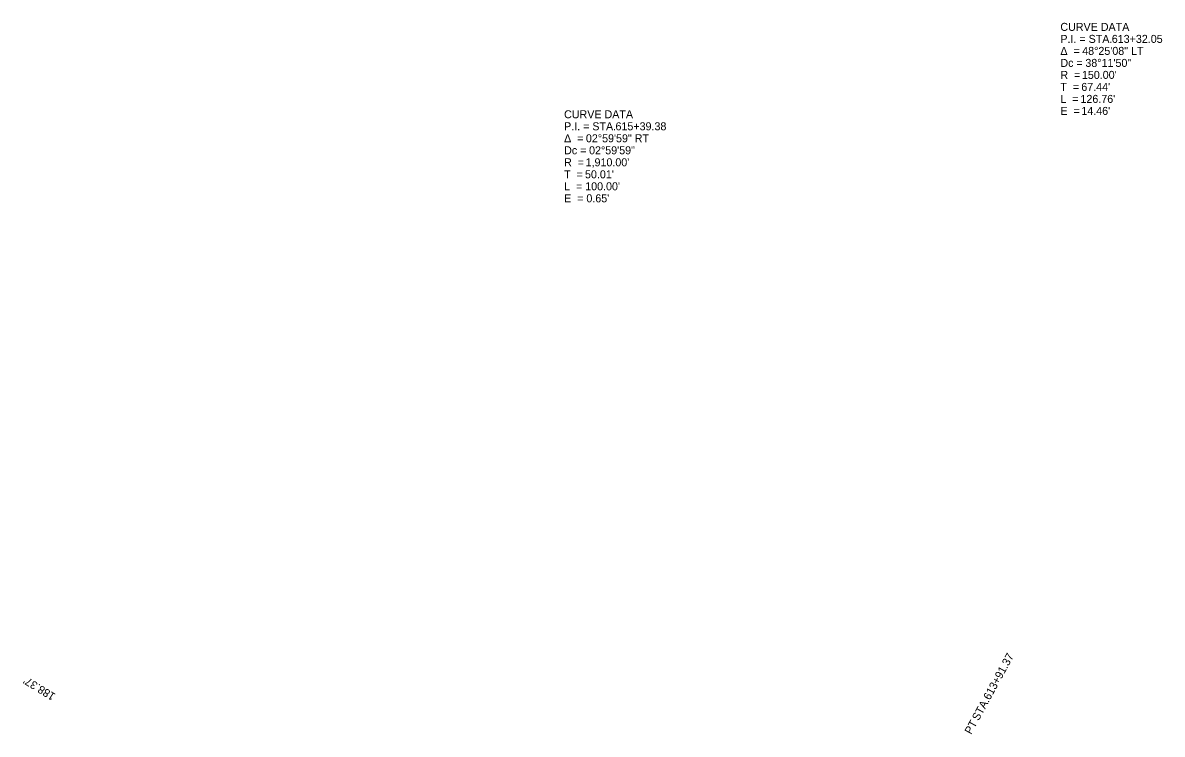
# Model space of a CAD drawing. Extents: x 1507135 to 1508660, y 327655 to 329219.
# Drawn here: x 1507283.8 to 1507682.5, y 328623.1 to 328872 of the extents above; entities that cross this region are included whole.
import ezdxf

# ---------------------------------------------------------------- set-up
doc = ezdxf.new("R2010")
doc.units = 0
for name, color, linetype in [('GE_X_Alignment_100_Cardinal_Points', 7, 'Continuous'), ('GE_X_Alignment_100_Curve_Data', 7, 'Continuous'), ('GE_X_Alignment_500_Curve_Data', 7, 'Continuous'), ('GE_X_Alignment_500_Distances', 7, 'Continuous')]:
    doc.layers.add(name, color=color, linetype=linetype)

msp = doc.modelspace()

# ---------------------------------------------------------------- texts
at = {"layer": 'GE_X_Alignment_100_Cardinal_Points'}
for s, p in [('613+91.37', (1507622.17, 328634.8)), (' STA. ', (1507617.71, 328626.62)), ('PT', (1507615.63, 328622.8))]:
    msp.add_text(s, height=2.8, rotation=61.3965, dxfattribs=at).set_placement(p)
at = {"layer": 'GE_X_Alignment_100_Curve_Data'}
for s, p in [('CURVE DATA', (1507473.2, 328838.6)), ('P.I. = STA. ', (1507473.2, 328834.4)), ('615+39.38', (1507491.19, 328834.4)), ('Δ  = ', (1507473.2, 328830.2)), ('02°59\'59" RT', (1507480.84, 328830.2)), ('Dc = ', (1507473.2, 328826)), ('02°59\'59"', (1507481.94, 328826)), ('R  = ', (1507473.2, 328821.8)), ("1,910.00'", (1507480.73, 328821.8)), ('T  = ', (1507473.2, 328817.6)), ("50.01'", (1507480.52, 328817.6)), ("L  = 100.00'", (1507473.2, 328813.4)), ("E  = 0.65'", (1507473.2, 328809.2))]:
    msp.add_text(s, height=2.8, dxfattribs=at).set_placement(p)
at = {"layer": 'GE_X_Alignment_500_Curve_Data'}
for s, p in [('CURVE DATA', (1507646.87, 328869.18)), ('P.I. = STA. ', (1507646.87, 328864.98)), ('613+32.05', (1507664.86, 328864.98)), ('Δ  = ', (1507646.87, 328860.78)), ('48°25\'08" LT', (1507654.51, 328860.78)), ('Dc = ', (1507646.87, 328856.58)), ('38°11\'50"', (1507655.61, 328856.58)), ('R  = ', (1507646.87, 328852.38)), ("150.00'", (1507654.4, 328852.38)), ('T  = ', (1507646.87, 328848.18)), ("67.44'", (1507654.19, 328848.18)), ('L  = ', (1507646.87, 328843.98)), ("126.76'", (1507653.9, 328843.98)), ('E  = ', (1507646.87, 328839.78)), ("14.46'", (1507654.21, 328839.78))]:
    msp.add_text(s, height=2.8, dxfattribs=at).set_placement(p)
at = {"layer": 'GE_X_Alignment_500_Distances'}
msp.add_text("188.37'", height=2.8, rotation=148.3965, dxfattribs=at).set_placement((1507295.45, 328637.05))

doc.saveas('drawing.dxf')
